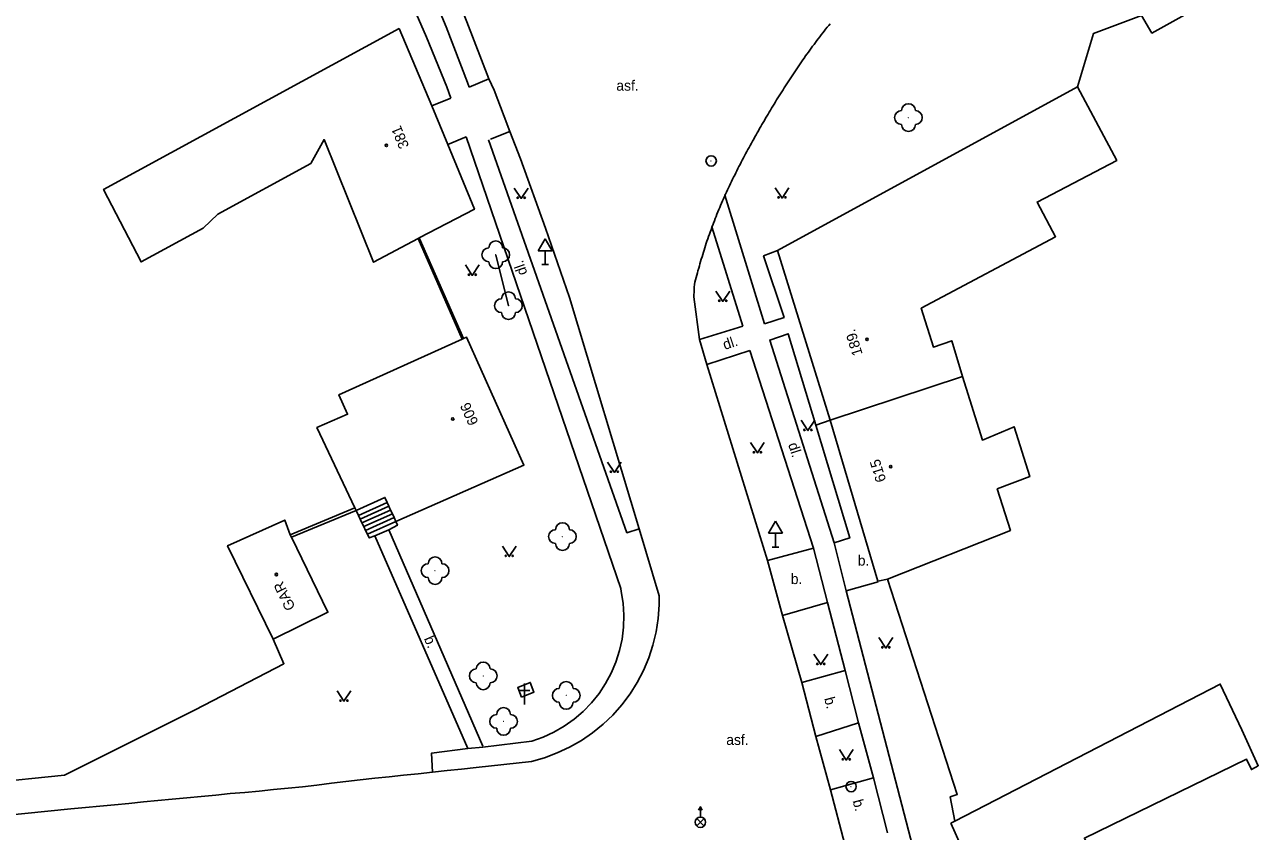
# Model space of a CAD drawing. Extents: x -536391 to -535419, y -1201788 to -1200779.
# Drawn here: x -535590.1 to -535501, y -1201602.5 to -1201544.3 of the extents above; entities that cross this region are included whole.
import ezdxf

# ---------------------------------------------------------------- set-up
doc = ezdxf.new("R2010")
doc.units = 0
for name, color, linetype in [('BUDOVY_MĚŘ', 7, 'Continuous'), ('BUDOVY_NEMĚŘ', 7, 'Continuous'), ('MAP_ZN_BP', 7, 'Continuous'), ('POMOC_POPIS', 7, 'Continuous'), ('ROZHRANÍ_PLOCH', 7, 'Continuous'), ('ZELEŇ', 7, 'Continuous'), ('ZN_BP', 7, 'Continuous'), ('ZN_BUDOV', 7, 'Continuous'), ('ZN_DOPLŇKOVÉ', 7, 'Continuous'), ('ZN_KULTUR', 7, 'Continuous'), ('Č_POPIS_ORIENT', 7, 'Continuous')]:
    doc.layers.add(name, color=color, linetype=linetype)

msp = doc.modelspace()

# ---------------------------------------------------------------- linework, layer by layer
at = {"layer": 'BUDOVY_MĚŘ'}
for points in [[(-535561.57, -1201559.65), (-535557.59, -1201557.59), (-535559.5, -1201552.92), (-535560.67, -1201550.12), (-535563.03, -1201544.54)], [(-535535.71, -1201560.57), (-535514.03, -1201548.76)], [(-535561.66, -1201559.7), (-535561.57, -1201559.65)], [(-535531.9, -1201572.83), (-535535.71, -1201560.57)], [(-535558.38, -1201566.94), (-535558.16, -1201566.84), (-535554.01, -1201576.07), (-535563.27, -1201580.14)], [(-535558.47, -1201566.98), (-535558.38, -1201566.94)], [(-535528.44, -1201584.45), (-535531.9, -1201572.83)], [(-535563.88, -1201578.78), (-535564.05, -1201578.41), (-535566.14, -1201579.35)], [(-535563.76, -1201579.05), (-535563.88, -1201578.78)], [(-535566.14, -1201579.35), (-535566.22, -1201579.17)], [(-535563.64, -1201579.32), (-535563.76, -1201579.05)], [(-535563.51, -1201579.6), (-535563.64, -1201579.32)], [(-535563.39, -1201579.87), (-535563.51, -1201579.6)], [(-535563.27, -1201580.14), (-535563.39, -1201579.87)], [(-535570.81, -1201581.28), (-535568.17, -1201586.7), (-535572.12, -1201588.65)], [(-535570.89, -1201581.11), (-535570.81, -1201581.28)], [(-535528.44, -1201584.45), (-535527.76, -1201584.32)], [(-535523.18, -1201601.94), (-535522.9, -1201601.79)], [(-535516.38, -1201617.2), (-535521.06, -1201606.7), (-535521.43, -1201605.87), (-535523.18, -1201601.94)]]:
    msp.add_lwpolyline(points, dxfattribs=at)
at = {"layer": 'BUDOVY_NEMĚŘ'}
for points in [[(-535509.4, -1201543.6), (-535508.65, -1201544.87), (-535506.27, -1201543.55), (-535509.62, -1201537.58)], [(-535563.03, -1201544.54), (-535584.37, -1201556.16), (-535581.66, -1201561.4), (-535577.17, -1201558.97), (-535576.12, -1201557.94), (-535569.4, -1201554.28), (-535568.45, -1201552.56), (-535564.87, -1201561.42), (-535561.66, -1201559.7)], [(-535522.34, -1201569.68), (-535523.11, -1201567.09), (-535524.44, -1201567.55), (-535525.31, -1201564.75), (-535515.61, -1201559.58), (-535516.95, -1201557.07), (-535511.2, -1201554.06), (-535514.03, -1201548.76)], [(-535558.47, -1201566.98), (-535567.38, -1201570.99), (-535566.75, -1201572.4), (-535568.96, -1201573.36), (-535566.22, -1201579.17)], [(-535527.76, -1201584.32), (-535518.87, -1201580.79), (-535519.83, -1201577.8), (-535517.48, -1201576.9), (-535518.61, -1201573.3), (-535520.9, -1201574.27), (-535522.34, -1201569.68), (-535531.9, -1201572.83)], [(-535570.89, -1201581.11), (-535571.29, -1201580.05), (-535575.42, -1201581.9), (-535572.12, -1201588.65)], [(-535511.42, -1201615.11), (-535512.76, -1201611.86), (-535510.13, -1201610.73), (-535513.53, -1201603.02), (-535501.82, -1201597.33), (-535501.47, -1201598.07), (-535500.97, -1201597.79), (-535502.17, -1201595.2), (-535503.72, -1201591.89), (-535522.9, -1201601.79)]]:
    msp.add_lwpolyline(points, dxfattribs=at)
at = {"layer": 'MAP_ZN_BP'}
for centre, radius in [((-535540.49, -1201554.1), 0.375), ((-535540.49, -1201554.1), 0.0005), ((-535530.38, -1201599.301), 0.375), ((-535530.38, -1201599.301), 0.0005)]:
    msp.add_circle(centre, radius, dxfattribs=at)
at = {"layer": 'ROZHRANÍ_PLOCH'}
for points in [[(-535559.28, -1201549.57), (-535559.59, -1201548.75), (-535561.04, -1201545.16), (-535567.24, -1201530.99), (-535567.78, -1201529.85), (-535568.21, -1201528.88), (-535572, -1201520.91), (-535578.88, -1201508.46), (-535580.82, -1201505.2), (-535588.58, -1201492.55)], [(-535566.65, -1201524.99), (-535563.37, -1201531.99), (-535558.46, -1201543.26), (-535558.14, -1201544.05), (-535556.54, -1201548.16)], [(-535557.96, -1201548.78), (-535558.09, -1201548.43), (-535559.64, -1201544.42), (-535559.94, -1201543.67), (-535565.46, -1201531.02), (-535568.06, -1201525.62)], [(-535531.89, -1201544.19), (-535532, -1201544.32), (-535532.11, -1201544.45), (-535532.22, -1201544.59), (-535532.33, -1201544.72), (-535532.43, -1201544.86), (-535532.54, -1201544.99), (-535532.65, -1201545.13), (-535532.75, -1201545.27), (-535532.86, -1201545.4), (-535532.96, -1201545.54), (-535533.06, -1201545.68), (-535533.17, -1201545.82), (-535533.27, -1201545.96), (-535533.37, -1201546.1), (-535533.47, -1201546.24), (-535533.57, -1201546.38), (-535533.67, -1201546.52), (-535533.77, -1201546.67), (-535533.87, -1201546.81), (-535533.97, -1201546.95), (-535534.07, -1201547.09), (-535534.16, -1201547.23), (-535534.26, -1201547.38), (-535534.36, -1201547.52), (-535534.45, -1201547.66), (-535534.55, -1201547.81), (-535534.65, -1201547.95), (-535534.74, -1201548.09), (-535534.84, -1201548.24), (-535534.93, -1201548.38), (-535535.02, -1201548.53), (-535535.12, -1201548.67), (-535535.21, -1201548.82), (-535535.3, -1201548.96), (-535535.39, -1201549.11), (-535535.49, -1201549.25), (-535535.58, -1201549.4), (-535535.67, -1201549.55), (-535535.76, -1201549.69)], [(-535557.96, -1201548.78), (-535556.54, -1201548.16)], [(-535556.54, -1201548.16), (-535556.17, -1201548.99), (-535555.44, -1201550.89)], [(-535559.28, -1201549.57), (-535560.67, -1201550.12)], [(-535535.76, -1201549.69), (-535535.85, -1201549.84), (-535535.94, -1201549.99), (-535536.03, -1201550.14), (-535536.12, -1201550.28), (-535536.2, -1201550.43), (-535536.29, -1201550.58), (-535536.38, -1201550.73), (-535536.47, -1201550.88), (-535536.56, -1201551.02), (-535536.64, -1201551.17), (-535536.73, -1201551.32), (-535536.82, -1201551.47), (-535536.9, -1201551.62), (-535536.99, -1201551.77), (-535537.07, -1201551.92), (-535537.16, -1201552.07), (-535537.25, -1201552.22), (-535537.33, -1201552.37), (-535537.41, -1201552.52), (-535537.5, -1201552.67), (-535537.58, -1201552.83), (-535537.67, -1201552.98), (-535537.75, -1201553.13), (-535537.83, -1201553.28), (-535537.91, -1201553.43), (-535538, -1201553.58), (-535538.08, -1201553.74), (-535538.16, -1201553.89), (-535538.24, -1201554.04), (-535538.32, -1201554.19), (-535538.4, -1201554.35), (-535538.48, -1201554.5), (-535538.56, -1201554.65), (-535538.64, -1201554.81), (-535538.71, -1201554.96), (-535538.79, -1201555.12), (-535538.87, -1201555.27), (-535538.94, -1201555.42), (-535539.02, -1201555.58), (-535539.09, -1201555.73), (-535539.17, -1201555.89), (-535539.24, -1201556.05), (-535539.31, -1201556.2), (-535539.39, -1201556.36), (-535539.46, -1201556.51), (-535539.49, -1201556.58)], [(-535555.44, -1201550.89), (-535555.04, -1201551.97)], [(-535555.04, -1201551.97), (-535556.43, -1201552.53)], [(-535555.04, -1201551.97), (-535554.27, -1201553.96), (-535552.45, -1201558.95), (-535550.71, -1201563.97), (-535545.7, -1201580.68)], [(-535558.19, -1201552.37), (-535559.5, -1201552.92)], [(-535556.97, -1201596.44), (-535553.45, -1201596.02), (-535552.63, -1201595.73), (-535551.85, -1201595.37), (-535551.1, -1201594.94), (-535550.39, -1201594.44), (-535549.74, -1201593.88), (-535549.13, -1201593.26), (-535548.59, -1201592.58), (-535548.11, -1201591.86), (-535547.7, -1201591.1), (-535547.37, -1201590.31), (-535547.11, -1201589.48), (-535546.92, -1201588.64), (-535546.81, -1201587.78), (-535546.79, -1201586.91), (-535546.84, -1201586.05), (-535546.98, -1201585.2), (-535547.02, -1201584.99), (-535558.19, -1201552.37)], [(-535545.7, -1201580.68), (-535546.57, -1201580.96), (-535556.56, -1201552.58)], [(-535539.49, -1201556.58), (-535539.53, -1201556.67), (-535539.6, -1201556.83), (-535539.67, -1201556.99), (-535539.74, -1201557.15), (-535539.81, -1201557.31), (-535539.87, -1201557.47), (-535539.94, -1201557.62), (-535540, -1201557.78), (-535540.07, -1201557.94), (-535540.13, -1201558.11), (-535540.19, -1201558.26), (-535540.25, -1201558.43), (-535540.31, -1201558.59), (-535540.38, -1201558.75), (-535540.43, -1201558.87)], [(-535536.64, -1201565.86), (-535539.49, -1201556.58)], [(-535540.43, -1201558.87), (-535540.5, -1201559.07), (-535540.56, -1201559.24), (-535540.62, -1201559.4), (-535540.67, -1201559.56), (-535540.73, -1201559.72), (-535540.79, -1201559.89), (-535540.84, -1201560.05), (-535540.89, -1201560.21), (-535540.95, -1201560.38), (-535541, -1201560.54), (-535541.05, -1201560.7), (-535541.1, -1201560.87), (-535541.15, -1201561.03), (-535541.2, -1201561.2), (-535541.25, -1201561.36), (-535541.3, -1201561.53), (-535541.34, -1201561.69), (-535541.39, -1201561.86), (-535541.44, -1201562.03), (-535541.48, -1201562.19), (-535541.53, -1201562.36), (-535541.57, -1201562.53), (-535541.61, -1201562.7), (-535541.66, -1201562.87), (-535541.69, -1201563.04), (-535541.71, -1201563.21), (-535541.72, -1201563.39), (-535541.72, -1201563.56), (-535541.75, -1201563.79), (-535541.73, -1201563.91)], [(-535538.2, -1201566.04), (-535540.43, -1201558.87)], [(-535535.71, -1201560.57), (-535536.7, -1201560.97), (-535535.22, -1201565.41), (-535536.64, -1201565.86)], [(-535541.73, -1201563.91), (-535541.33, -1201567.01)], [(-535541.33, -1201567.01), (-535538.2, -1201566.04)], [(-535541.33, -1201567.01), (-535540.8, -1201568.81)], [(-535532.94, -1201573.19), (-535534.92, -1201566.59), (-535536.26, -1201567.04), (-535531.61, -1201581.69)], [(-535540.8, -1201568.81), (-535537.7, -1201567.79)], [(-535537.7, -1201567.79), (-535533.09, -1201582.08)], [(-535540.8, -1201568.81), (-535536.43, -1201582.96)], [(-535531.9, -1201572.83), (-535532.94, -1201573.19)], [(-535531.61, -1201581.69), (-535530.48, -1201581.33), (-535532.94, -1201573.19)], [(-535565.97, -1201579.71), (-535563.88, -1201578.78)], [(-535566.14, -1201579.35), (-535565.97, -1201579.71)], [(-535565.97, -1201579.71), (-535565.84, -1201579.98)], [(-535565.84, -1201579.98), (-535563.76, -1201579.05)], [(-535565.71, -1201580.25), (-535563.64, -1201579.32)], [(-535565.58, -1201580.52), (-535563.51, -1201579.6)], [(-535565.84, -1201579.98), (-535565.71, -1201580.25)], [(-535565.71, -1201580.25), (-535565.58, -1201580.52)], [(-535565.58, -1201580.52), (-535565.45, -1201580.8)], [(-535565.45, -1201580.8), (-535563.39, -1201579.87)], [(-535563.27, -1201580.14), (-535565.32, -1201581.07)], [(-535565.32, -1201581.07), (-535565.19, -1201581.34), (-535564.79, -1201581.19), (-535563.76, -1201580.74), (-535563.15, -1201580.42), (-535563.27, -1201580.14)], [(-535556.98, -1201596.39), (-535563.76, -1201580.74)], [(-535545.7, -1201580.68), (-535544.25, -1201585.52), (-535544.25, -1201586.18), (-535544.32, -1201587.16), (-535544.47, -1201588.13), (-535544.7, -1201589.08), (-535545, -1201590.01), (-535545.38, -1201590.91), (-535545.83, -1201591.78), (-535546.35, -1201592.61), (-535546.94, -1201593.39), (-535547.59, -1201594.13), (-535548.3, -1201594.8), (-535549.06, -1201595.42), (-535549.86, -1201595.97), (-535550.71, -1201596.46), (-535551.6, -1201596.87), (-535552.52, -1201597.22), (-535553.46, -1201597.48), (-535557.47, -1201597.91), (-535558.52, -1201598.03), (-535559.56, -1201598.14), (-535560.61, -1201598.25)], [(-535565.45, -1201580.8), (-535565.32, -1201581.07)], [(-535558.07, -1201596.56), (-535564.79, -1201581.19)], [(-535536.43, -1201582.96), (-535533.09, -1201582.08)], [(-535532.08, -1201585.99), (-535533.09, -1201582.08)], [(-535530.74, -1201585.15), (-535531.61, -1201581.69)], [(-535536.43, -1201582.96), (-535535.33, -1201586.94)], [(-535528.42, -1201584.52), (-535530.74, -1201585.15)], [(-535530.74, -1201585.15), (-535525.02, -1201607.19), (-535521.43, -1201605.87)], [(-535535.33, -1201586.94), (-535532.08, -1201585.99)], [(-535532.08, -1201585.99), (-535530.82, -1201590.92)], [(-535533.95, -1201591.78), (-535535.33, -1201586.94)], [(-535533.95, -1201591.78), (-535530.82, -1201590.92)], [(-535530.82, -1201590.92), (-535529.85, -1201594.69)], [(-535554.19, -1201592.84), (-535554.46, -1201592.14), (-535553.56, -1201591.78), (-535553.29, -1201592.48), (-535554.19, -1201592.84)], [(-535532.94, -1201595.69), (-535533.95, -1201591.78)], [(-535532.94, -1201595.69), (-535529.85, -1201594.69)], [(-535529.85, -1201594.69), (-535528.76, -1201598.67)], [(-535531.87, -1201599.53), (-535532.94, -1201595.69)], [(-535560.61, -1201598.25), (-535560.69, -1201596.89), (-535558.07, -1201596.56)], [(-535558.07, -1201596.56), (-535556.97, -1201596.44)], [(-535560.61, -1201598.25), (-535561.65, -1201598.37), (-535562.7, -1201598.48), (-535563.74, -1201598.59), (-535564.78, -1201598.7), (-535565.83, -1201598.82), (-535566.87, -1201598.93), (-535567.92, -1201599.06), (-535568.96, -1201599.19), (-535570, -1201599.31), (-535571.05, -1201599.42), (-535572.09, -1201599.51), (-535573.14, -1201599.62), (-535574.18, -1201599.72), (-535575.23, -1201599.81), (-535576.27, -1201599.91), (-535577.32, -1201600.01), (-535578.37, -1201600.11), (-535579.41, -1201600.21), (-535580.46, -1201600.31), (-535581.5, -1201600.41), (-535582.55, -1201600.51), (-535583.59, -1201600.61), (-535584.64, -1201600.71), (-535585.68, -1201600.81), (-535586.73, -1201600.91), (-535601.96, -1201602.45)], [(-535531.87, -1201599.53), (-535528.76, -1201598.67)], [(-535528.76, -1201598.67), (-535527.76, -1201602.65)], [(-535530.83, -1201603.48), (-535531.87, -1201599.53)]]:
    msp.add_lwpolyline(points, dxfattribs=at)
at = {"layer": 'ZELEŇ'}
msp.add_lwpolyline([(-535556.05, -1201560.88), (-535555.13, -1201564.56)], dxfattribs=at)
for centre in [(-535526.24, -1201550.97), (-535556.05, -1201560.88), (-535555.13, -1201564.56), (-535551.23, -1201581.24), (-535560.43, -1201583.7), (-535556.95, -1201591.3), (-535550.96, -1201592.71), (-535555.48, -1201594.59)]:
    msp.add_circle(centre, 0.0005, dxfattribs=at)
for centre, start, end in [((-535526.24, -1201550.47), 0, 179.99999), ((-535526.74, -1201550.97), 89.99999, 269.99999), ((-535525.74, -1201550.97), 270, 89.99999), ((-535526.24, -1201551.47), 179.99999, 359.99999), ((-535556.05, -1201560.38), 0, 179.99999), ((-535556.55, -1201560.88), 89.99999, 269.99999), ((-535555.55, -1201560.88), 270, 89.99999), ((-535556.05, -1201561.38), 179.99999, 359.99999), ((-535555.13, -1201564.06), 0, 179.99999), ((-535555.63, -1201564.56), 89.99999, 269.99999), ((-535554.63, -1201564.56), 270, 89.99999), ((-535555.13, -1201565.06), 179.99999, 359.99999), ((-535551.73, -1201581.24), 89.99999, 269.99999), ((-535551.23, -1201580.74), 0, 179.99999), ((-535550.73, -1201581.24), 270, 89.99999), ((-535551.23, -1201581.74), 179.99999, 359.99999), ((-535560.93, -1201583.7), 89.99999, 269.99999), ((-535560.43, -1201583.2), 0, 179.99999), ((-535559.93, -1201583.7), 270, 89.99999), ((-535560.43, -1201584.2), 179.99999, 359.99999), ((-535556.95, -1201590.8), 0, 179.99999), ((-535557.45, -1201591.3), 89.99999, 269.99999), ((-535556.45, -1201591.3), 270, 89.99999), ((-535556.95, -1201591.8), 179.99999, 359.99999), ((-535551.46, -1201592.71), 89.99999, 269.99999), ((-535550.96, -1201592.21), 0, 179.99999), ((-535550.46, -1201592.71), 270, 89.99999), ((-535550.96, -1201593.21), 179.99999, 359.99999), ((-535555.98, -1201594.59), 89.99999, 269.99999), ((-535555.48, -1201594.09), 0, 179.99999), ((-535554.98, -1201594.59), 270, 89.99999), ((-535555.48, -1201595.09), 179.99999, 359.99999)]:
    msp.add_arc(centre, 0.5, start, end, dxfattribs=at)
at = {"layer": 'ZN_BP'}
for p, q in [((-535541.27, -1201601.505), (-535541.27, -1201600.755)), ((-535541.535, -1201602.144), (-535541.006, -1201601.616)), ((-535541.006, -1201602.148), (-535541.535, -1201601.616))]:
    msp.add_line(p, q, dxfattribs=at)
msp.add_lwpolyline([(-535541.395, -1201601.005), (-535541.27, -1201600.755), (-535541.145, -1201601.005)], dxfattribs=at)
msp.add_circle((-535541.27, -1201601.88), 0.375, dxfattribs=at)
at = {"layer": 'ZN_BUDOV'}
for p, q in [((-535553.96, -1201593.36), (-535553.96, -1201591.86)), ((-535554.335, -1201592.36), (-535553.585, -1201592.36))]:
    msp.add_line(p, q, dxfattribs=at)
for centre in [(-535563.95, -1201552.98), (-535529.23, -1201566.99), (-535559.15, -1201572.74), (-535527.52, -1201576.19), (-535571.89, -1201583.98)]:
    msp.add_circle(centre, 0.0875, dxfattribs=at)
at = {"layer": 'ZN_DOPLŇKOVÉ'}
for p, q in [((-535552.48, -1201559.724), (-535552.98, -1201560.59)), ((-535552.48, -1201559.724), (-535551.98, -1201560.59)), ((-535552.98, -1201560.59), (-535551.98, -1201560.59)), ((-535552.48, -1201561.59), (-535552.48, -1201560.59)), ((-535552.73, -1201561.59), (-535552.23, -1201561.59)), ((-535535.84, -1201580.134), (-535536.34, -1201581)), ((-535535.84, -1201580.134), (-535535.34, -1201581)), ((-535536.34, -1201581), (-535535.34, -1201581)), ((-535535.84, -1201582), (-535535.84, -1201581)), ((-535536.09, -1201582), (-535535.59, -1201582))]:
    msp.add_line(p, q, dxfattribs=at)
for points in [[(-535509.4, -1201543.6), (-535512.88, -1201544.9), (-535514.03, -1201548.76)], [(-535558.47, -1201566.98), (-535561.66, -1201559.7)], [(-535558.38, -1201566.94), (-535561.57, -1201559.65)], [(-535570.89, -1201581.11), (-535566.22, -1201579.17)], [(-535570.81, -1201581.28), (-535566.14, -1201579.35)], [(-535527.76, -1201584.32), (-535522.72, -1201599.86), (-535523.22, -1201600.05), (-535522.9, -1201601.79)], [(-535572.12, -1201588.65), (-535571.35, -1201590.42), (-535577.76, -1201593.75), (-535587.2, -1201598.48), (-535604.18, -1201600.22)]]:
    msp.add_lwpolyline(points, dxfattribs=at)
at = {"layer": 'ZN_KULTUR'}
for points in [[(-535554.71, -1201556.06), (-535554.21, -1201556.81), (-535553.71, -1201556.06)], [(-535535.87, -1201556.04), (-535535.37, -1201556.79), (-535534.87, -1201556.04)], [(-535558.24, -1201561.62), (-535557.74, -1201562.37), (-535557.24, -1201561.62)], [(-535540.15, -1201563.5), (-535539.65, -1201564.25), (-535539.15, -1201563.5)], [(-535534, -1201572.83), (-535533.5, -1201573.58), (-535533, -1201572.83)], [(-535537.65, -1201574.45), (-535537.15, -1201575.2), (-535536.65, -1201574.45)], [(-535547.98, -1201575.86), (-535547.48, -1201576.61), (-535546.98, -1201575.86)], [(-535555.57, -1201581.93), (-535555.07, -1201582.68), (-535554.57, -1201581.93)], [(-535528.37, -1201588.54), (-535527.87, -1201589.29), (-535527.37, -1201588.54)], [(-535533.07, -1201589.74), (-535532.57, -1201590.49), (-535532.07, -1201589.74)], [(-535567.51, -1201592.39), (-535567.01, -1201593.14), (-535566.51, -1201592.39)], [(-535531.23, -1201596.63), (-535530.73, -1201597.38), (-535530.23, -1201596.63)]]:
    msp.add_lwpolyline(points, dxfattribs=at)
for centre in [(-535535.62, -1201556.74), (-535535.12, -1201556.74), (-535554.46, -1201556.76), (-535553.96, -1201556.76), (-535557.99, -1201562.32), (-535557.49, -1201562.32), (-535539.9, -1201564.2), (-535539.4, -1201564.2), (-535533.75, -1201573.53), (-535533.25, -1201573.53), (-535537.4, -1201575.15), (-535536.9, -1201575.15), (-535547.73, -1201576.56), (-535547.23, -1201576.56), (-535555.32, -1201582.63), (-535554.82, -1201582.63), (-535528.12, -1201589.24), (-535527.62, -1201589.24), (-535532.82, -1201590.44), (-535532.32, -1201590.44), (-535567.26, -1201593.09), (-535566.76, -1201593.09), (-535530.98, -1201597.33), (-535530.48, -1201597.33)]:
    msp.add_circle(centre, 0.05, dxfattribs=at)

# ---------------------------------------------------------------- texts
at = {"layer": 'POMOC_POPIS'}
for s, p in [('asf.', (-535547.34, -1201549.03)), ('b.', (-535529.9, -1201583.34)), ('b.', (-535534.74, -1201584.67)), ('asf.', (-535539.4, -1201596.29))]:
    msp.add_text(s, height=0.75, dxfattribs=at).set_placement(p)
for s, rotation, p in [('dl.', 109.36, (-535553.75, -1201562.22)), ('dl.', 18.20997, (-535539.5, -1201567.76)), ('dl.', 287.88001, (-535534.94, -1201574.58)), ('GAR', 115.92999, (-535570.5, -1201586.36)), ('b.', 293.62001, (-535561.25, -1201588.61)), ('b.', 284.48002, (-535532.33, -1201592.93)), ('b.', 284.75, (-535530.28, -1201600.33))]:
    msp.add_text(s, height=0.75, rotation=rotation, dxfattribs=at).set_placement(p)
at = {"layer": 'Č_POPIS_ORIENT'}
for s, rotation, p in [('381', 112.58002, (-535562.29, -1201553.03)), ('189.', 107.40002, (-535529.54, -1201568.05)), ('606', 114.16998, (-535557.28, -1201573)), ('615', 107.27002, (-535527.84, -1201577.18))]:
    msp.add_text(s, height=0.75, rotation=rotation, dxfattribs=at).set_placement(p)

doc.saveas('drawing.dxf')
